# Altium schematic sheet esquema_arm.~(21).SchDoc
size A4
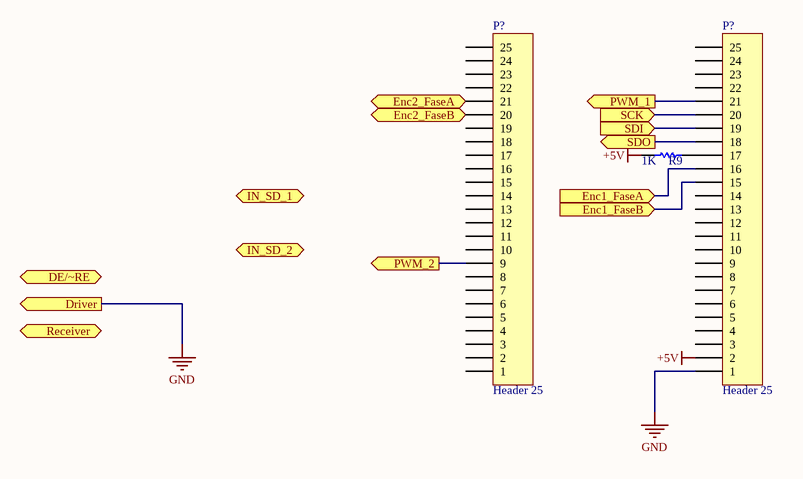
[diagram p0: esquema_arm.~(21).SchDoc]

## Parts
(Parts that share a designator on the sheet are numbered #1, #2 ... from top to bottom, then left to right.)
P?#1  Header 25  [HDR1X25]
P?#2  Header 25  [HDR1X25]
R9  value 1K  [AXIAL-0.3]  (hidden comment: Res Semi)

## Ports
DE/~RE (out), Driver (out), Enc1_FaseA (in), Enc1_FaseB (in), Enc2_FaseA (in), Enc2_FaseB (in), IN_SD_1 (out), IN_SD_2 (out), PWM_1 (out), PWM_2 (out), Receiver (in), SCK (in), SDI (in), SDO (out)

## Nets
+5V: P?#2.2 R9.1
GND: P?#2.1 ; port Driver
Enc1_FaseA: P?#2.16 ; port Enc1_FaseA
Enc1_FaseB: P?#2.15 ; port Enc1_FaseB
Enc2_FaseA: P?#1.21 ; port Enc2_FaseA
Enc2_FaseB: P?#1.20 ; port Enc2_FaseB
PWM_1: P?#2.21 ; port PWM_1
PWM_2: P?#1.9 ; port PWM_2
SCK: P?#2.20 ; port SCK
SDI: P?#2.19 ; port SDI
SDO: P?#2.18 ; port SDO
NetP?#2_17: P?#2.17 R9.2

Not connected (* = marked no-connect by the designer): P?#1 1 2 3 4 5 6 7 8 10 11 12 13 14 15 16 17 18 19 22 23 24 25; P?#2 3 4 5 6 7 8 9 10 11 12 13 14 22 23 24 25

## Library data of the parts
P?#1 P?#2 = Header 25: Header, 25-Pin
R9 = Res Semi: Semiconductor Resistor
